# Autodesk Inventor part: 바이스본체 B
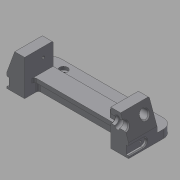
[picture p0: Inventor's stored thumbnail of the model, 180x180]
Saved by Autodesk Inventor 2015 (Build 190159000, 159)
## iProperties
Created: 2017-04
Part Number: 바이스본체 B
Material: 일반
Document SubType Name: Modeling
Designer: mduedu
Density: 1 g/cm^3
Appearance: 기본값
Author: mduedu
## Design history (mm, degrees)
sketch "스케치1"
  geometry: L1 (-75, 0)-(75, 0); L2 (-75, 0)-(-75, 17); L3 (-53, 17)-(53, 17); L4 (75, 17)-(75, 0); L5 (-75, 17)-(-65.173, 44); L6 (-65.173, 44)-(-53, 44); L7 (-53, 44)-(-53, 17); L8 (0, 0)-(0, 17); L9 (75, 17)-(65.173, 44); L10 (65.173, 44)-(53, 44); L11 (53, 44)-(53, 17); 1 further point
  constraints: 22 end point, 4 perpendicular, 2 horizontal alignment, 2 midpoint, 2 symmetric about line, 1 coincident, 1 collinear, 1 horizontal, 1 vertical
  dimensions: "d0" = 150 distance of L1.start L1.end; "d1" = 17 distance of L1.start L2.end; "d2" = 27 distance of L3.start L6.end; "d3" = 22 distance of L3.start L2.end; "d4" = 70 deg angle of L3 L5; "d54" = 20 deg angle of L9 L4
extrude "돌출1" new body sketch "스케치1" stored distance "d5" = 70; taper "d6" = 0 deg
sketch "스케치2"
  geometry: L1 (0, 70)-(106, 70) reference; L2 (106, 70)-(106, 0) reference; L3 (106, 0)-(0, 0) reference; L4 (0, 47)-(106, 47); L5 (106, 47)-(106, 23); L6 (106, 23)-(0, 23); L7 (0, 23)-(0, 47); L8 (0, 70)-(0, 0) reference; 2 further points
  constraints: 8 end point, 2 parallel, 2 point on line, 1 horizontal, 1 horizontal alignment, 1 midpoint, 1 perpendicular
  dimensions: "d7" = 24 distance between parallel lines of L6 L4
extrude "돌출2" cut sketch "스케치2" stored distance "d9" = 70; taper "d10" = 0 deg
sketch "스케치3"
  geometry: L1 (22, -23)-(128, -23) reference; L2 (128, -47)-(22, -47) reference; L3 (22, -18)-(128, -18); L4 (128, -52)-(22, -52); L5 (22, -18)-(22, -52); L6 (128, -18)-(128, -52); 1 further point
  constraints: 8 end point, 3 parallel, 2 point on line, 1 perpendicular
  dimensions: "d11" = 5 distance between parallel lines of L3 L1; "d12" = 5 distance between parallel lines of L4 L2
extrude "돌출3" cut sketch "스케치3" distance "d13" = 12; taper "d14" = 0 deg
fillet "모깎기1" dims "d15" = 3, "d16" = 3
sketch "스케치4"
  geometry: L1 (103, 23)-(3, 23) reference; L2 (0, 26)-(0, 0) reference; L3 (106, 0)-(0, 0) reference; L4 (106, 26)-(106, 0) reference; L5 (96, 0)-(90, 0); L6 (90, 0)-(90, 19.5); L7 (96, 19.5)-(96, 0); L8 (90, 19.5)-(96, 19.5); A1 r 3 centre (3, 26) between (0, 26) and (3, 23) reference; A2 r 3 centre (103, 26) between (103, 23) and (106, 26) reference; 1 further point
  constraints: 8 end point, 2 perpendicular, 1 horizontal, 1 parallel, 1 point on line
  dimensions: "d17" = 10 distance between parallel lines of L7 L4; "d18" = 6 distance between parallel lines of L7 L6; "d27" = 3.5 distance between parallel lines of L8 L1
extrude "돌출4" join sketch "스케치4" distance "d19" = 12; taper "d20" = 0 deg
chamfer "모따기1" distance "d21" = 3; stored, may be unused: second distance "d22" = 2, angle "d23" = 45 deg
chamfer "모따기2" distance "d24" = 3; stored, may be unused: second distance "d25" = 2, angle "d26" = 45 deg
sketch "스케치5"
  geometry: L1 (-15.5, 35.8)-(-15.5, -25.8) reference; L2 (19.5, 0)-(0, 0) reference; C1 r 6.5 at (9.5, 15); 1 further point
  constraints: 1 centre point
  dimensions: "d28" = 13 diameter of C1; "d30" = 15 distance from line of C1.centre L2; "d31" = 25 distance from line of C1.centre L1
extrude "돌출5" cut sketch "스케치5" stored distance "d32" = 12; taper "d33" = 0 deg
sketch "스케치6"
  geometry: C1 r 5 at (-10, 15); C2 r 5 at (-60, 15); A1 r 6.5 centre (-10, 15) between (-15.766, 12) and (-4.234, 12) reference; A2 r 6.5 centre (-60, 15) between (-65.766, 12) and (-54.234, 12) reference; 1 further point
  constraints: 2 centre point, 2 coincident
  dimensions: "d34" = 10 diameter of C1; "d35" = 10 diameter of C2 (= d34)
extrude "돌출6" cut sketch "스케치6" stored distance "d36" = 12; taper "d37" = 0 deg
chamfer "모따기3" distance "d38" = 1; stored, may be unused: second distance "d39" = 2, angle "d40" = 45 deg
chamfer "모따기4" distance "d41" = 1; stored, may be unused: second distance "d42" = 2, angle "d43" = 45 deg
sketch "스케치7"
  geometry: L1 (-35, 35.8)-(-35, -25.8) reference; L2 (-70, 0)-(0, 0) reference; C1 r 5 at (-35, 15); 1 further point
  constraints: 1 centre point, 1 point on line
  dimensions: "d44" = 10 diameter of C1; "d45" = 15 distance from line of C1.centre L2
extrude "돌출7" cut sketch "스케치7" stored distance "d46" = 12; taper "d47" = 0 deg
chamfer "모따기5" distance "d48" = 1; stored, may be unused: second distance "d49" = 2, angle "d50" = 45 deg
node "작업축1"
sketch "스케치8"
  geometry: L1 (-105, 32)-(105, 32) reference; L2 (58, 32)-(64, 32); L3 (64, 32)-(64, 40); L4 (64, 40)-(58, 40); L5 (58, 40)-(58, 32); L6 (53, 38)-(53, 26) reference; 1 further point
  constraints: 8 end point, 2 parallel, 1 horizontal, 1 perpendicular, 1 point on line
  dimensions: "d51" = 5 distance from line of L6 L2.start; "d52" = 6 distance of L3.end L4.end; "d53" = 16 diameter of L4 L1
revolve "회전1" sketch "스케치8" stored, may be unused: angle "d55" = 90 deg
fillet "모깎기2"
chamfer "모따기6" distance "d56" = 1; stored, may be unused: second distance "d57" = 2, angle "d58" = 45 deg
sketch "스케치9"
  geometry: L1 (17.5, 3)-(52.5, 3); L2 (52.5, 13)-(17.5, 13); L3 (70, 0)-(0, 0) reference; L4 (17.5, 8)-(52.5, 8); A1 r 5 centre (17.5, 8) between (17.5, 13) and (17.5, 3); A2 r 5 centre (52.5, 8) between (52.5, 3) and (52.5, 13); 3 further points
  constraints: 6 end point, 4 point on circle, 3 tangent, 2 centre point, 2 midpoint, 2 parallel, 1 horizontal, 1 vertical alignment
  dimensions: "d59" = 35 distance of L4.start L4.end; "d61" = 5 radius of A2; "d62" = 8 distance between parallel lines of L3 L4
extrude "돌출8" cut sketch "스케치9" distance "d63" = 3; taper "d64" = 0 deg
chamfer "모따기7" distance "d65" = 1; stored, may be unused: second distance "d66" = 2, angle "d67" = 45 deg
chamfer "모따기8" distance "d68" = 1; stored, may be unused: second distance "d69" = 2, angle "d70" = 45 deg
feature "분할1"
sketch "스케치10"
  geometry: A1 r 5 centre (0, 0) between (0, 5) and (0, -5) reference; 1 further point
  constraints: 1 coincident
hole "구멍1" sketch "스케치10" at (0, 0) diameter "d71" = 2.459; stored, may be unused: countersink angle "d75" = 90 deg, drill point angle "d77" = 120 deg; dims "d72" = 4.5, "d73" = 4, "d74" = 2, "d76" = 6
sketch "스케치11"
  geometry: L1 (0, 0)-(0, 27) reference; L2 (0, 27)-(-35, 27) reference; 2 further points
  dimensions: "d78" = 12 distance from line of point (-12, 15.5) L1; "d79" = 11.5 distance from line of point (-12, 15.5) L2
hole "구멍2" sketch "스케치11" at (-12, 15.5) diameter "d80" = 3.242; stored, may be unused: countersink angle "d84" = 90 deg, drill point angle "d86" = 120 deg; dims "d81" = 6, "d82" = 4, "d83" = 2, "d85" = 8
sketch "스케치12"
  geometry: L1 (-75, -35)-(-75, 0) reference; L2 (75, -35)-(75, 0) reference; L3 (75, -35)-(-75, -35); L4 (-75, -35)-(-75, -55); L5 (-75, -55)-(75, -55); L6 (75, -55)-(75, -35); 1 further point
  constraints: 8 end point, 2 parallel, 1 horizontal, 1 perpendicular, 1 point on line
  dimensions: "d87" = 20 distance of L3.end L4.end; "d89" = 150 distance of L4.end L5.end (derived)
extrude "돌출9" join sketch "스케치12" distance "d90" = 10; taper "d91" = 0 deg
sketch "스케치13"
  geometry: L1 (-75, 55)-(-75, 35) reference; L2 (75, 35)-(75, 55) reference; L3 (-75, 45)-(75, 45); 3 further points
  constraints: 2 end point, 2 midpoint, 2 point on line
  dimensions: "d92" = 50 horizontal distance of point (-50, 45) point (0, 0); "d93" = 100 distance of point (50, 45) point (-50, 45)
fillet "모깎기3" dims "d94" = 12
chamfer "모따기9" distance "d95" = 1; stored, may be unused: second distance "d96" = 2, angle "d97" = 45 deg
hole "구멍3" sketch "스케치13" diameter "d98" = 4.134; stored, may be unused: countersink angle "d102" = 90 deg, drill point angle "d104" = 118 deg; dims "d99" = 6, "d100" = 10, "d101" = 4, "d103" = 8
node "솔리드1"
mirror "대칭1"
mirror "대칭2"
mirror "대칭3"
mirror "대칭4"
node "투영된 루프1"
